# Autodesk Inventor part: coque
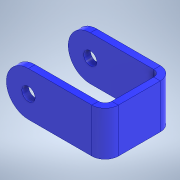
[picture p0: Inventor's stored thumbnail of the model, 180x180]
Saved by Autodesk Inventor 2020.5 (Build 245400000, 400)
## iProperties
Created: 2022-10
Part Number: coque
Material: Plastique PMMA
Document SubType Name: Tôle
Designer: mel
Density: 1.188 g/cm^3
Sheet Metal Rule: Par défaut_mm
Appearance: Bleu - Peinture murale - Brillant
Flat Pattern Width: 2 cm
Flat Pattern Length: 11 cm
Flat Pattern Area: 22 cm^2
Sheet Metal Width: 20,000 mm
Sheet Metal Length: 110,000 mm
Sheet Metal Area: 2200,000 mm^2
Author: mel
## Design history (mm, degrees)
node "Face1"
  sketch "Esquisse1"
    geometry: L1 (-7, 0)-(83, 0); L2 (83, -20)-(-7, -20); C1 r 3 at (-7, -10); C2 r 3 at (83, -10); A1 r 10 centre (-7, -10) between (-7, 0) and (-7, -20); A2 r 10 centre (83, -10) between (83, -20) and (83, 0); 1 further point
    constraints: 4 centre point, 4 end point, 4 point on circle, 3 tangent, 2 coincident, 1 horizontal, 1 parallel
    dimensions: "d2" = 10 radius of A2; "d3" = 10 radius of A1 (derived); "d5" = 6 diameter of C1; "d6" = 6 diameter of C2; "d32" = 90 distance of A2.centre A1.centre
sketch "Esquisse2"
  geometry: L1 (25.107, 0)-(25.107, -20); L2 (-7, 0)-(83, 0) reference; L3 (83, -20)-(-7, -20) reference; C1 r 3 at (83, -10) reference; C2 r 3 at (-7, -10) reference; A1 r 10 centre (83, -10) between (83, -20) and (83, 0) reference; A2 r 10 centre (-7, -10) between (-7, 0) and (-7, -20) reference; 1 further point
  constraints: 2 end point, 2 point on line, 1 vertical
  dimensions: "d8" = 32.107 distance from line of L1 C2.centre
feature "Pliage1" sketch "Esquisse2" dims "d7" = 3 (= Epaisseur), "d10" = 3 (= LargeurGrugeage), "d11" = 1.5 (= ProfondeurGrugeage), "d12" = 6 (= RestesMinimum), "d13" = 3 (= Rayondetransition), "d14" = 90 deg, "d15" = 3 (= RayonPli), "JeuJointure" = 0.01
sketch "Esquisse3"
  geometry: L1 (-54.5, 10)-(-54.5, -10) reference; L2 (0, -10)-(-54.5, -10) reference; L3 (-54.5, 10)-(0, 10) reference; L4 (-54.5, 10)-(0, 10) reference; L5 (-32.107, 10)-(-32.107, -10); L6 (0, -10)-(-54.5, -10) reference; C1 r 3 at (0, 0) reference; A1 r 10 centre (0, 0) between (0, -10) and (0, 10) reference; 1 further point
  constraints: 2 end point, 2 point on line, 1 perpendicular
  dimensions: "d16" = 32.107 distance from line of L5 A1.centre (= d8)
feature "Pliage2" sketch "Esquisse3" dims "d7" = 3 (= Epaisseur), "d17" = 3 (= LargeurGrugeage), "d18" = 1.5 (= ProfondeurGrugeage), "d19" = 6 (= RestesMinimum), "d20" = 3 (= Rayondetransition), "d21" = 90 deg, "d22" = 3 (= RayonPli), "JeuJointure" = 0.01
node "Solide1"
feature "Plaque1" dims "d7" = 3 (= Epaisseur)
node "Boucle projetée1"
node "Boucle projetée2"
feature "Définition1"
other parameters: "Epaisseur" = 3 (derived), "FacteurX" = 4.4, "RayonPli" = 3 (= Epaisseur), "LargeurGrugeage" = 3 (= Epaisseur), "ProfondeurGrugeage" = 1.5 (= 0.5 x Epaisseur), "TailleGrugeage" = 12 (= 4 x Epaisseur), "RestesMinimum" = 6 (= 2 x Epaisseur), "Rayondetransition" = 3 (= RayonPli), "TailleRayonJacobi" = 3 (= RayonPli), "TailleJeu" = 3 (= Epaisseur), "Epaisseur" = 3, "LargeurGrugeage" = 3, "ProfondeurGrugeage" = 1.5, "RayonPli" = 3, "Rayondetransition" = 3, "RestesMinimum" = 6, "TailleGrugeage" = 12, "TailleJeu" = 3, "TailleRayonJacobi" = 3
